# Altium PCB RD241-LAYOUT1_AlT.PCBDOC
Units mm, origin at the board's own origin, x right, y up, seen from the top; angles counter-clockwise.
Board outline 20 x 20 mm, 2 copper layers (TOP, BOTTOM), stack 0 mm thick; 24 components, 14 nets, 115 pads, 0 vias.
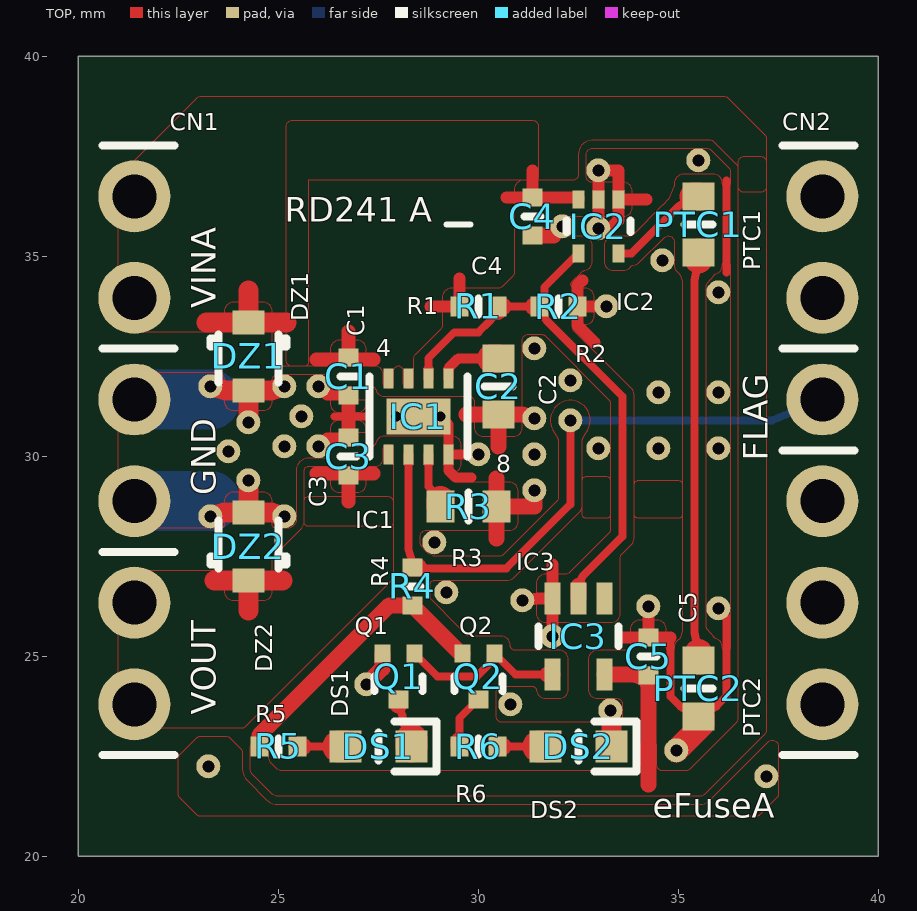
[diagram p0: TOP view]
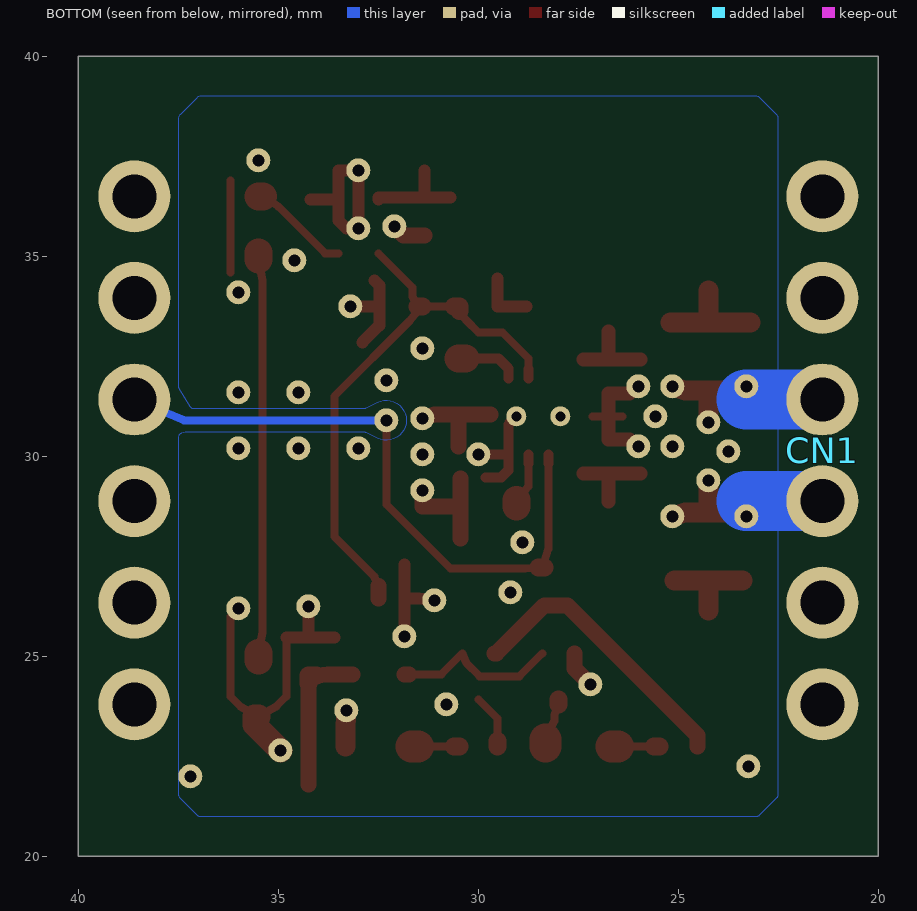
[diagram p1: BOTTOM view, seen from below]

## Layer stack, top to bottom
Top Solder: solder mask 0.0102, Solder Resist, Dk 3.5
TOP: signal copper (thickness not stored)
BOTTOM: signal copper (thickness not stored)
Bottom Solder: solder mask 0.0102, Solder Resist, Dk 3.5

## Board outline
20,20 20,40 40,40 40,20

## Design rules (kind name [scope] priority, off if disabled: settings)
AssemblyTestPointUsage [All] p0: scope1count=1 scope1_0_kind=Board scope1_0_value=Board scope2count=1 scope2_0_kind=Board scope2_0_value=Board commentlength=0
AssemblyTestpoint [All] p0: scope1count=1 scope1_0_kind=Board scope1_0_value=Board scope2count=1 scope2_0_kind=Board scope2_0_value=Board commentlength=0
Clearance [All] p0: scope1count=1 scope1_0_kind=Board scope1_0_value=Board scope2count=1 scope2_0_kind=Board scope2_0_value=Board commentlength=0 gap=0.2
Clearance [All] p1: gap=0.2 ignorepadtopadclearanceinfootprint=TRUE except(1: Arc-Hole Track-Hole SMDPad-Hole THPad-Hole Via-Hole Fill-Hole Poly-Hole Region-Hole Text-Hole)
ComponentClearance [All] p0: scope1count=1 scope1_0_kind=Board scope1_0_value=Board scope2count=1 scope2_0_kind=Board scope2_0_value=Board commentlength=0 gap=0.254 collisioncheckmode=3
DiffPairsRouting [All] p0: scope1count=1 scope1_0_kind=Board scope1_0_value=Board scope2count=1 scope2_0_kind=Board scope2_0_value=Board commentlength=0
FabricationTestPointUsage [All] p0: scope1count=1 scope1_0_kind=Board scope1_0_value=Board scope2count=1 scope2_0_kind=Board scope2_0_value=Board commentlength=0 valid=0 allowmultiple=FALSE
FabricationTestpoint [All] p0: scope1count=1 scope1_0_kind=Board scope1_0_value=Board scope2count=1 scope2_0_kind=Board scope2_0_value=Board commentlength=0 side=3 testpointundercomponent=TRUE minsize=1.016 maxsize=2.54 preferedsize=1.524 minholesize=0 maxholesize=1.016 preferedholesize=0.813 testpointgrid=0.025
FanoutControl Fanout_BGA [All] p0 off: scope1count=1 scope1_0_kind=Board scope1_0_value=Board scope2count=1 scope2_0_kind=Board scope2_0_value=Board commentlength=69 // Protel DXP Scope 1 Expression Was: IsBGA   Fanout_BGA (Default Rule)
FanoutControl Fanout_LCC [All] p0 off: scope1count=1 scope1_0_kind=Board scope1_0_value=Board scope2count=1 scope2_0_kind=Board scope2_0_value=Board commentlength=69 // Protel DXP Scope 1 Expression Was: IsLCC   Fanout_LCC (Default Rule)
FanoutControl Fanout_SOIC [All] p0 off: scope1count=1 scope1_0_kind=Board scope1_0_value=Board scope2count=1 scope2_0_kind=Board scope2_0_value=Board commentlength=71 // Protel DXP Scope 1 Expression Was: IsSOIC   Fanout_SOIC (Default Rule)
FanoutControl Fanout_Small [All] p0 off: scope1count=1 scope1_0_kind=Board scope1_0_value=Board scope2count=1 scope2_0_kind=Board scope2_0_value=Board commentlength=84 // Protel DXP Scope 1 Expression Was: (CompPinCount < 5)   Fanout_Small (Default Rule)
FanoutControl Fanout_Default [All] p0: scope1count=1 scope1_0_kind=Board scope1_0_value=Board scope2count=1 scope2_0_kind=Board scope2_0_value=Board commentlength=30 // Fanout_Default (Default Rule)
Height [All] p0: scope1count=1 scope1_0_kind=Board scope1_0_value=Board scope2count=1 scope2_0_kind=Board scope2_0_value=Board commentlength=0
HoleSize [All] p0: scope1count=1 scope1_0_kind=Board scope1_0_value=Board scope2count=1 scope2_0_kind=Board scope2_0_value=Board commentlength=0 absolutevalues=TRUE maxlimit=100 minlimit=0.001 maxpercent=80.000 minpercent=20.000
HoleSize [All] p1: absolutevalues=TRUE maxlimit=100 minlimit=0.001 maxpercent=80.000 minpercent=20.000
HoleToHoleClearance [All] p0: scope1count=1 scope1_0_kind=Board scope1_0_value=Board scope2count=1 scope2_0_kind=Board scope2_0_value=Board commentlength=0
HoleToHoleClearance [All] p1: gap=0.5 allowstackedmicrovias=FALSE
LayerPairs [All] p0: scope1count=1 scope1_0_kind=Board scope1_0_value=Board scope2count=1 scope2_0_kind=Board scope2_0_value=Board commentlength=0 enforce=TRUE
MinimumSolderMaskSliver [All] p0: scope1count=1 scope1_0_kind=Board scope1_0_value=Board scope2count=1 scope2_0_kind=Board scope2_0_value=Board commentlength=0
MinimumSolderMaskSliver [All] p1: minsoldermaskwidth=0.1
NetAntennae [All] p0: scope1count=1 scope1_0_kind=Board scope1_0_value=Board scope2count=1 scope2_0_kind=Board scope2_0_value=Board commentlength=0
NetAntennae [All] p1: netantennaetolerance=100
PasteMaskExpansion [All] p0: scope1count=1 scope1_0_kind=Board scope1_0_value=Board scope2count=1 scope2_0_kind=Board scope2_0_value=Board commentlength=0 expansion=0
PlaneClearance [All] p0: scope1count=1 scope1_0_kind=Board scope1_0_value=Board scope2count=1 scope2_0_kind=Board scope2_0_value=Board commentlength=0 clearance=0.001
PlaneClearance [All] p1: clearance=0.001
PlaneConnect [All] p0: scope1count=1 scope1_0_kind=Board scope1_0_value=Board scope2count=1 scope2_0_kind=Board scope2_0_value=Board commentlength=0 planeconnectstyle=Direct reliefexpansion=0.508 reliefentries=4 reliefconductorwidth=0.254 reliefairgap=0.254
PlaneConnect [All] p1: planeconnectstyle=Direct reliefexpansion=0.508 reliefentries=4 reliefconductorwidth=0.254 reliefairgap=0.254
PolygonConnect [All] p0: scope1count=1 scope1_0_kind=Board scope1_0_value=Board scope2count=1 scope2_0_kind=Board scope2_0_value=Board commentlength=0 connectstyle=Direct reliefconductorwidth=0.254 reliefentries=4 polygonreliefangle="90 Angle"
PolygonConnect [All] p1: connectstyle=Direct reliefconductorwidth=0.254 reliefentries=4 polygonreliefangle="90 Angle" airgapwidth=0.254
RoutingCorners [All] p0: scope1count=1 scope1_0_kind=Board scope1_0_value=Board scope2count=1 scope2_0_kind=Board scope2_0_value=Board commentlength=0 cornerstyle=45-Degree minsetback=2.54 maxsetback=2.54
RoutingLayers [All] p0: scope1count=1 scope1_0_kind=Board scope1_0_value=Board scope2count=1 scope2_0_kind=Board scope2_0_value=Board commentlength=0 top layer=Automatic bottom layer=Automatic
RoutingPriority [All] p0: scope1count=1 scope1_0_kind=Board scope1_0_value=Board scope2count=1 scope2_0_kind=Board scope2_0_value=Board commentlength=0
RoutingTopology [All] p0: scope1count=1 scope1_0_kind=Board scope1_0_value=Board scope2count=1 scope2_0_kind=Board scope2_0_value=Board commentlength=0 topology=Shortest
RoutingVias [All] p0: scope1count=1 scope1_0_kind=Board scope1_0_value=Board scope2count=1 scope2_0_kind=Board scope2_0_value=Board commentlength=0 holewidth=0.1 width=0.1 viastyle="Through Hole" minholewidth=0.001 minwidth=0.001 maxholewidth=100 maxwidth=100
RoutingVias [All] p1: holewidth=0.1 width=0.1 viastyle="Through Hole" minholewidth=0.001 minwidth=0.001 maxholewidth=100 maxwidth=100
ShortCircuit [All] p0: scope1count=1 scope1_0_kind=Board scope1_0_value=Board scope2count=1 scope2_0_kind=Board scope2_0_value=Board commentlength=0 allowed=FALSE
SilkToBoardRegionClearance [All] p0: scope1count=1 scope1_0_kind=Board scope1_0_value=Board scope2count=1 scope2_0_kind=Board scope2_0_value=Board commentlength=0
SilkToSilkClearance [All] p0: scope1count=1 scope1_0_kind=Board scope1_0_value=Board scope2count=1 scope2_0_kind=Board scope2_0_value=Board commentlength=0
SilkToSilkClearance [All] p1: silktosilkclearance=0.001
SilkToSolderMaskClearance [All] p0 off: scope1count=1 scope1_0_kind=Board scope1_0_value=Board scope2count=1 scope2_0_kind=Board scope2_0_value=Board commentlength=44 // Protel DXP Scope 1 Expression Was: IsPad
SilkToSolderMaskClearance [IsPad] p1: minsilkscreentomaskgap=0.05 clearancetoexposedcopper=TRUE
SolderMaskExpansion [All] p0: scope1count=1 scope1_0_kind=Board scope1_0_value=Board scope2count=1 scope2_0_kind=Board scope2_0_value=Board commentlength=0 expansion=0.001
SolderMaskExpansion [All] p1: expansion=0.001
UnRoutedNet [All] p0: scope1count=1 scope1_0_kind=Board scope1_0_value=Board scope2count=1 scope2_0_kind=Board scope2_0_value=Board commentlength=0
UnpouredPolygon [All] p0: scope1count=1 scope1_0_kind=Board scope1_0_value=Board scope2count=1 scope2_0_kind=Board scope2_0_value=Board commentlength=0
Width [All] p0: scope1count=1 scope1_0_kind=Board scope1_0_value=Board scope2count=1 scope2_0_kind=Board scope2_0_value=Board commentlength=0 maxlimit=1000 minlimit=2539.975 preferedwidth=0
Width [All] p1: maxlimit=1000 minlimit=2539.975 preferedwidth=0 toplayer_minwidth=0 bottomlayer_minwidth=0 minimp=50.000000 maximp=50.000000 favimp=50.000000
22 further rules are at their usual default settings.

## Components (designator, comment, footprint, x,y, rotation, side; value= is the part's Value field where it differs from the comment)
C1 "Chip1005_GS_2" Chip1005_GS_2 26.75,32 r270 top
C2 "Chip1608_GS_1" Chip1608_GS_1 30.5,31.75 r270 top
C3 "Chip1005_GS_2" Chip1005_GS_2 26.75,30 r90 top
C4 "Chip1005_GS_2" Chip1005_GS_2 31.35,36 r270 top
C5 "Chip1005_GS_2" Chip1005_GS_2 34.25,25 r90 top
CN1 "CN_I_TSW-106-07-*-S_SAMTEC" CN_I_TSW-106-07-*-S_SAMTEC 21.4,30.15 r90 bottom
DS1 "LD_S_APT1608_KB_1K-3A" LD_S_APT1608_KB_1K-3A 27.5,22.75 r180 top
DS2 "LD_S_APT1608_KB_1K-3A" LD_S_APT1608_KB_1K-3A 32.5,22.75 r180 top
DZ1 "DI_S_ESC_TS_1A-3K" DI_S_ESC_TS_1A-3K 24.25,32.5 r90 top
DZ2 "DI_S_ESC_TS_1A-3K" DI_S_ESC_TS_1A-3K 24.25,27.75 r270 top
IC1 "IC_S_SON_TCKE905NA_TS" IC_S_SON_TCKE905NA_TS 28.5,31 r180 top
IC2 "IC_S_SMD_ESV_TS" IC_S_SMD_ESV_TS 33,35.75 r180 top
IC3 "IC_S_SMD_USV_TS" IC_S_SMD_USV_TS 32.5,25.5 r180 top
PTC1 "Chip1608_GS_1" Chip1608_GS_1 35.5,35.8 r90 top
PTC2 "Chip1608_GS_1" Chip1608_GS_1 35.5,24.2 r90 top
Q1 "FET_S_VESM_TS_2G-3S-1D" FET_S_VESM_TS_2G-3S-1D 28,24.5 r180 top
Q2 "FET_S_VESM_TS_2G-3S-1D" FET_S_VESM_TS_2G-3S-1D 30,24.5 r180 top
R1 "Chip1005_GS_2" Chip1005_GS_2 30,33.75 r180 top
R2 "Chip1005_GS_2" Chip1005_GS_2 32,33.75 r180 top
R3 "Chip1608_GS_1" Chip1608_GS_1 29.75,28.75 r180 top
R4 "Chip1005_GS_2" Chip1005_GS_2 28.35,26.75 r270 top
R5 "Chip1005_GS_2" Chip1005_GS_2 25,22.75 r180 top
R6 "Chip1005_GS_2" Chip1005_GS_2 30,22.75 r180 top
? "CN_I_TSW-106-07-*-S_SAMTEC" CN_I_TSW-106-07-*-S_SAMTEC 38.6,30.15 r270 bottom

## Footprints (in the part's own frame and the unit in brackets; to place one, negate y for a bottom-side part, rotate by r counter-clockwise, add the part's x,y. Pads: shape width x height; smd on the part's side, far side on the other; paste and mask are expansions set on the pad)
Chip1005_GS_2 [mm] "KC00080BKP"
  rect 0.45x0.5 smd paste-0.6 mask+0: 1(-0.475,0) 2(0.475,0)
  silkscreen extent 0,-0.2 0,0.2
Chip1608_GS_1 [mm] "KC00080BKP"
  rect 0.7x0.8 smd paste-0.9 mask+0: 1(-0.7,0) 2(0.7,0)
  silkscreen extent 0,-0.35 0,0.35
CN_I_TSW-106-07-*-S_SAMTEC [mm] "KC00080BKP"
  round 1.8 / inner round 0 / far side round 1.8 hole 1.1 paste-1.9 mask+0: 1(6.35,0) 2(3.81,0) 3(1.27,0) 4(-1.27,0) 5(-3.81,0) 6(-6.35,0)
DI_S_ESC_TS_1A-3K [mm] "KC00080BKP"
  rect 0.6x0.8 smd paste-0.9 mask+0: 1(-0.85,0) 3(0.85,0)
  silkscreen extent -0.65,-0.95 0.55,0.95
FET_S_VESM_TS_2G-3S-1D [mm] "KC00080BKP"
  rect 0.5x0.45 smd paste-0.6 mask+0: 1(0,0.575)
  rect 0.4x0.45 smd paste-0.55 mask+0: 2(-0.4,-0.575) 3(0.4,-0.575)
  silkscreen extent -0.6,0 0.6,0.37
IC_S_SMD_ESV_TS [mm] "KC00080BKP"
  rect 0.3x0.45 smd paste-0.55 mask+0: 1(-0.5,-0.675) 2(0,-0.675) 3(0.5,-0.675) 4(0.5,0.675) 5(-0.5,0.675)
  silkscreen extent -0.8,-0.14 0.8,0.14
IC_S_SMD_USV_TS [mm] "KC00080BKP"
  rect 0.4x0.8 smd paste-0.9 mask+0: 1(-0.65,-0.95) 2(0,-0.95) 3(0.65,-0.95) 4(0.65,0.95) 5(-0.65,0.95)
  silkscreen extent -1,-0.24 1,0.24
IC_S_SON_TCKE905NA_TS [mm] "KC00080BKP"
  rect 0.25x0.5 smd paste-0.6 mask+0: 1(-0.75,-0.95) 2(-0.25,-0.95) 3(0.25,-0.95) 4(0.75,-0.95) 5(0.75,0.95) 6(0.25,0.95) 7(-0.25,0.95) 8(-0.75,0.95)
  rect 1.6x0.9 smd paste-1.7 mask+0: 9(0,0)
  silkscreen extent -1.23,-1 1.22,1
LD_S_APT1608_KB_1K-3A [mm] "KC00080BKP"
  rect 0.8x0.8 smd paste-0.9 mask+0: 1(-0.825,0) 3(0.825,0)
  silkscreen extent 0,-0.35 0,0.35

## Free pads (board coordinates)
  round 0.6 / inner round 0 / far side round 0.6 hole 0.3 paste-0.6 mask+0: ""(23.25,22.25) ""(23.3,28.5) ""(23.3,31.75) ""(23.75,30.125) ""(24.25,29.4) ""(24.25,30.85) ""(25.15,28.5) ""(25.15,30.25) ""(25.15,31.75) ""(25.575,31) ""(26,30.25) ""(26,31.75) ""(27.2,24.3) ""(28.9,27.85) ""(29.2,26.6) ""(30,30.05) ""(30.8,23.8) ""(31.1,26.4) ""(31.4,29.15) ""(31.4,30.05) ""(31.4,30.95) ""(31.4,32.7) ""(31.85,25.5) ""(32.1,35.75) ""(32.3,30.9) ""(32.3,31.9) ""(33,30.2) ""(33,35.7) ""(33,37.15) ""(33.2,33.75) ""(33.3,23.65) ""(34.25,26.25) ""(34.5,30.2) ""(34.5,31.6) ""(34.6,34.9) ""(34.95,22.65) ""(35.5,37.4) ""(36,26.2) ""(36,30.2) ""(36,31.6) ""(36,34.1) ""(37.2,22)
  round 0.5 / inner round 0 / far side round 0.5 hole 0.25 paste-0.5 mask+0: ""(27.95,31) ""(29.05,31)

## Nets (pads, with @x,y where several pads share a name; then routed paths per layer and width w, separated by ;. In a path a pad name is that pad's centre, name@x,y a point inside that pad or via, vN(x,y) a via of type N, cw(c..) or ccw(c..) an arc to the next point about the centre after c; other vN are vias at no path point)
FLAG_A: ?.4 IC1.6 pad.@32.3,30.9 R4.1 | length 15.8
  TOP w0.2: IC1.6@28.25,29.819 28.25,27.689 R4.1@28.35,27.367 ; R4.1@28.492,27.225 28.828,27.2 30.7,27.2 32.3,28.8 pad.@32.3,30.9
  TOP w0.25: IC1.6@28.25,29.819 IC1.6
  TOP w0.45: R4.1 R4.1@28.492,27.225
  BOTTOM w0.2: pad.@32.3,30.9 37.354,30.9 ?.4
GND_A: C1.2 C2.2 C3.2 C4.2 C5.2 CN1.3 CN1.4 DS2.1 DZ1.1 DZ2.1 IC1.8 IC1.9 IC2.1 IC2.2 IC3.3 pad.@23.3,28.5 pad.@23.3,31.75 pad.@23.25,22.25 pad.@23.75,30.125 pad.@24.25,29.4 pad.@24.25,30.85 pad.@25.15,28.5 pad.@25.15,30.25 pad.@25.15,31.75 pad.@25.575,31 pad.@26,30.25 pad.@26,31.75 pad.@27.2,24.3 pad.@27.95,31 pad.@28.9,27.85 pad.@29.2,26.6 pad.@29.05,31 pad.@30,30.05 pad.@30.8,23.8 pad.@31.1,26.4 pad.@31.4,29.15 pad.@31.4,30.05 pad.@31.4,30.95 pad.@31.4,32.7 pad.@31.85,25.5 pad.@32.1,35.75 pad.@32.3,31.9 pad.@33,30.2 pad.@33,35.7 pad.@33,37.15 pad.@33.2,33.75 pad.@33.3,23.65 pad.@34.5,30.2 pad.@34.5,31.6 pad.@34.6,34.9 pad.@34.25,26.25 pad.@34.95,22.65 pad.@35.5,37.4 pad.@36,26.2 pad.@36,30.2 pad.@36,31.6 pad.@36,34.1 pad.@37.2,22 PTC2.1 Q1.3 R2.1 R3.1 | length 43.2
  TOP w0.2: 26.4,31 26.75,31 27.15,31 ; 34.8,25.475 34.8,24 35.05,23.75 PTC2.1 35.95,23.75 36.2,24 pad.@36.2,26 ; 36.2,34.6 36.2,36.9
  TOP w0.25: pad.@29.05,31 29.25,30.8 IC1.8 ; 29.825,29.475 29.425,29.475 29.25,29.65 IC1.8 ; pad.@30,30.05 IC1.8
  TOP w0.3: pad.@31.1,26.4 31.487,26.45 IC3.3 ; pad.@31.85,25.5 IC3.3 ; 31.85,27.3 IC3.3 ; 32.6,34.4 32.475,34.275 R2.1 ; 32.9,32.85 32.475,33.275 R2.1 ; pad.@33.2,33.75 R2.1 ; 33.6,25.475 C5.2 ; 34.2,36.425 IC2.1 ; pad.@34.25,26.25 C5.2 ; 34.8,25.475 C5.2 ; IC2.1 33.5,35.9 33.3,35.7 33,35.7 IC2.2 33,37.15 33.5,37.15 IC2.1
  TOP w0.35: pad.@26.225,30.425 26.75,30.425 C3.2 26.75,31 C1.2 26.75,31.575 pad.@26.225,31.575
  TOP w0.4: pad.@27.2,24.3 27.6,24.7 Q1.3 ; 29.7,31.05 C2.2 ; 30.45,27.95 R3.1 ; 30.45,29.45 R3.1 ; 30.5,30.25 C2.2 ; C4.2 31.875,35.525 pad.@32.1,35.75 ; pad.@31.4,29.15 31.4,28.75 R3.1 ; pad.@31.4,30.95 31.086,31.05 C2.2
  TOP w0.5: pad.@23.3,28.5 23.677,28.6 DZ2.1 ; pad.@23.3,31.75 23.677,31.65 DZ1.1 ; pad.@24.25,29.4 DZ2.1 ; pad.@24.25,30.85 DZ1.1 ; pad.@25.15,28.5 24.836,28.6 DZ2.1 ; pad.@25.15,31.75 24.836,31.65 DZ1.1 ; pad.@33.3,23.65 33.325,23.261 DS2.1
  TOP w0.6: pad.@34.95,22.65 35.6,23.3 35.6,23.5 PTC2.1
  BOTTOM w1.5: CN1.4 23.3,28.88 ; CN1.3 23.3,31.42
N439568: IC1.2 IC2.4 IC3.2 R1.1 R2.2 | length 14.1
  TOP w0.2: IC1.2@28.75,32.181 28.75,32.45 29.4,33.1 30,33.1 30.297,33.397 R1.1@30.475,33.629 ; R1.1@30.604,33.75 R2.2@31.396,33.75 ; R2.2@31.525,33.621 31.707,33.393 33.6,31.5 33.6,27.992 32.6,26.992 IC3.2@32.5,26.752 ; R2.2 31.65,34.014 31.65,34.225 IC2.4
  TOP w0.25: IC1.2 IC1.2@28.75,32.181
  TOP w0.4: IC3.2 IC3.2@32.5,26.752
  TOP w0.45: R1.1@30.475,33.629 R1.1 R1.1@30.604,33.75 ; R2.2@31.396,33.75 R2.2
N439874: C2.1 IC1.1 | length 1.6
  TOP w0.25: IC1.1 29.25,32.2 29.5,32.45 C2.1@30.323,32.45
  TOP w0.7: C2.1@30.323,32.45 C2.1
N440585: IC2.5 PTC1.2 | length 2.6
  TOP w0.2: IC2.5 33.828,35.075 35.003,36.25 PTC1.2@35.383,36.5
  TOP w0.7: PTC1.2@35.383,36.5 PTC1.2
N440589: PTC1.1 PTC2.2 | length 10.2
  TOP w0.2: PTC2.2@35.5,25.083 35.4,25.599 35.4,34.401 PTC1.1@35.5,34.917
  TOP w0.7: PTC2.2 PTC2.2@35.5,25.083 ; PTC1.1@35.5,34.917 PTC1.1
N441229: IC3.4 Q1.2 Q2.2 | length 4.2
  TOP w0.2: Q1.2 28.975,24.5 29.965,24.5 30.3,24.835 Q2.2 30.925,24.55 IC3.4@31.727,24.55
  TOP w0.4: IC3.4@31.727,24.55 IC3.4
N442165: Q2.1 R6.2 | length 1.4
  TOP w0.2: R6.2@29.525,22.879 29.525,23.45 Q2.1
  TOP w0.45: R6.2 R6.2@29.525,22.879
N444370: IC1.7 R3.2 | length 1.4
  TOP w0.2: IC1.7@28.75,29.819 28.75,29.25 R3.2@29.05,28.908
  TOP w0.25: IC1.7@28.75,29.819 IC1.7
  TOP w0.7: R3.2 R3.2@29.05,28.908
N450467: DS1.3 R5.1 | length 1.2
  TOP w0.2: R5.1@25.604,22.75 DS1.3@26.506,22.75
  TOP w0.45: R5.1 R5.1@25.604,22.75
  TOP w0.8: DS1.3@26.506,22.75 DS1.3
N450546: DS1.1 Q1.1 | length 1.2
  TOP w0.2: Q1.1@28,23.796 28.1,23.521 28.1,23.388 DS1.1@28.325,22.919
  TOP w0.45: Q1.1@28,23.796 Q1.1
  TOP w0.8: DS1.1 DS1.1@28.325,22.919
N475569: DS2.3 R6.1 | length 1.2
  TOP w0.2: R6.1@30.604,22.75 DS2.3@31.506,22.75
  TOP w0.45: R6.1 R6.1@30.604,22.75
  TOP w0.8: DS2.3@31.506,22.75 DS2.3
VINA_A: C1.1 C4.1 C5.1 CN1.1 CN1.2 DZ1.3 IC1.3 IC1.4 IC2.3 IC3.5 Q2.3 R1.2 R4.2 R5.2 | length 19.9
  TOP w0.3: 28.8,33.75 R1.2 29.525,34.45 ; 30.7,36.475 C4.1 ; 31.35,37.15 C4.1 ; IC2.3 32.5,36.475 C4.1
  TOP w0.35: 25.95,32.425 C1.1@26.75,32.425 ; 26.75,33.125 C1.1 C1.1@26.75,32.425 ; 27.375,32.425 C1.1@26.75,32.425
  TOP w0.4: R5.2 24.525,23.025 27.775,26.275 R4.2 29.55,25.075 Q2.3 ; IC3.5 33.753,24.55 C5.1@34.044,24.525 ; 34.25,21.8 C5.1@34.25,24.319
  TOP w0.45: C5.1@34.044,24.525 C5.1 C5.1@34.25,24.319
  TOP w0.5: 23.2,33.35 DZ1.3 ; 24.25,34.15 DZ1.3 ; 25.2,33.35 DZ1.3
VOUT_A: C3.1 CN1.5 CN1.6 DZ2.3 IC1.5 | length 4.6
  TOP w0.35: 25.95,29.575 C3.1@26.75,29.575 ; 26.75,28.875 C3.1 C3.1@26.75,29.575 ; 27.375,29.575 C3.1@26.75,29.575
  TOP w0.5: 23.4,26.9 DZ2.3 ; 24.25,26.15 DZ2.3 ; 25.1,26.9 DZ2.3
pads on no net: ?.1 ?.2 ?.3 ?.5 ?.6 IC3.1

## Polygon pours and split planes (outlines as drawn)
GND_A on TOP "TOP1" (solid, pour order 3): 23.041,21 cw(c23.041,21.1) 22.971,21.029 22.529,21.471 cw(c22.6,21.541) 22.5,21.541 22.5,22.459 cw(c22.6,22.459) 22.529,22.529 22.971,22.971 cw(c23.041,22.9) 23.041,23 23.688,23 cw(c23.688,22.85) 23.794,22.956 24.056,22.694 cw(c23.95,22.588) 24.1,22.588 24.1,22.183 ccw(c24.5,22.183) 24.217,21.9 24.7,21.417 ccw(c24.983,21.7) 24.983,21.3 35.5,21.3 cw(c35.505,21.2) 35.505,21.3 35.538,21.3 ccw(c35.538,21.65) 35.786,21.403 37.244,22.861 cw(c37.35,22.755) 37.5,22.755 37.5,21.541 cw(c37.4,21.541) 37.471,21.471 37.029,21.029 cw(c36.959,21.1) 36.959,21
VINA_A on TOP "TOP2" (solid, pour order 4): 24.983,21.5 cw(c24.983,21.7) 24.841,21.559 24.359,22.041 cw(c24.5,22.183) 24.3,22.183 24.3,22.7 cw(c24.5,22.7) 24.5,22.9 24.55,22.9 cw(c24.55,22.7) 24.75,22.7 24.75,22.483 ccw(c24.95,22.483) 24.809,22.341 24.941,22.209 ccw(c25.083,22.35) 25.083,22.15 33.9,22.15 ccw(c33.9,22.3) 34.05,22.3 34.05,22.75 cw(c34.2,22.75) 34.2,22.9 34.3,22.9 cw(c34.3,22.75) 34.45,22.75 34.45,22.3 ccw(c34.6,22.3) 34.6,22.15 35.188,22.15 ccw(c35.188,22.3) 35.294,22.194 36.456,23.356 ccw(c36.35,23.462) 36.5,23.462 36.5,23.94 36.5,23.942 36.5,23.95 36.5,26 36.5,26.006 36.5,26.008 36.5,26.8 36.5,37.35 cw(c36.65,37.35) 36.65,37.5 37.05,37.5 cw(c37.05,37.35) 37.2,37.35 37.2,23.162 cw(c37.05,23.162) 37.156,23.056 35.644,21.544 cw(c35.538,21.65) 35.538,21.5
VOUT_A on TOP "TOP3" (solid, pour order 5): 21.2,23.2 cw(c21.2,23.4) 21,23.4 21,26.95 cw(c21.2,26.95) 21.2,27.15 23.45,27.15 cw(c23.45,26.95) 23.65,26.95 23.65,26.625 ccw(c23.875,26.625) 23.875,26.4 24.625,26.4 ccw(c24.625,26.625) 24.85,26.625 24.85,27.405 cw(c25,27.405) 24.894,27.511 25.548,28.165 ccw(c25.3,28.412) 25.65,28.412 25.65,28.9 cw(c25.75,28.9) 25.75,29 27.725,29 cw(c27.725,28.85) 27.875,28.85 27.875,27.003 cw(c27.725,27.003) 27.831,26.897 24.178,23.244 cw(c24.072,23.35) 24.072,23.2 21.2,23.2
GND_A on TOP "TOP4" (solid, pour order 6): 30.6,23.35 cw(c30.6,23.5) 30.45,23.5 30.45,24.1 cw(c30.6,24.1) 30.6,24.25 31.351,24.25 cw(c31.351,24.15) 31.451,24.158 31.451,24.157 ccw(c31.675,24.175) 31.675,23.95 32.025,23.95 ccw(c32.025,24.175) 32.25,24.175 32.25,24.925 ccw(c32.025,24.925) 32.025,25.15 30.925,25.15 cw(c30.925,25.275) 30.8,25.275 ccw(c30.575,25.275) 30.575,25.5 29.803,25.5 cw(c29.803,25.65) 29.697,25.544 29.158,26.082 29.157,26.083 28.844,26.397 cw(c28.95,26.503) 28.8,26.503 28.8,26.8 cw(c28.9,26.8) 28.9,26.9 30.7,26.9 ccw(c30.7,27.2) 30.912,26.988 32.512,28.588 ccw(c32.3,28.8) 32.6,28.8 32.6,29.4 cw(c32.7,29.4) 32.7,29.5 33.2,29.5 cw(c33.2,29.4) 33.3,29.4 33.3,28.158 cw(c33.2,28.158) 33.271,28.087 32.389,27.206 32.389,27.205 32.271,27.088 cw(c32.2,27.159) 32.258,27.078 cw(c32.171,27.2) 32.171,27.05 31.675,27.05 ccw(c31.675,26.825) 31.45,26.825 31.45,26.075 ccw(c31.675,26.075) 31.675,25.85 33.325,25.85 ccw(c33.325,26.075) 33.55,26.075 33.55,27.456 cw(c33.7,27.456) 33.594,27.562 33.595,27.563 33.811,27.779 33.812,27.78 33.813,27.781 ccw(c33.6,27.992) 33.9,27.992 33.9,29.3 cw(c34,29.3) 34,29.4 35,29.4 cw(c35,29.3) 35.1,29.3 35.1,25.66 cw(c35,25.66) 35.095,25.63 35.044,25.468 cw(c34.949,25.498) 35.02,25.428 cw(c34.949,25.498) 35.003,25.414 ccw(c35.125,25.225) 34.9,25.23 cw(c34.8,25.232) 34.7,25.232 34.7,25.675 ccw(c34.475,25.675) 34.475,25.9 34.025,25.9 ccw(c34.025,25.675) 33.8,25.675 33.8,25.3 cw(c33.65,25.3) 33.65,25.15 32.975,25.15 ccw(c32.975,24.925) 32.75,24.925 32.75,24.175 ccw(c32.975,24.175) 32.975,23.95 33.45,23.95 cw(c33.45,23.8) 33.6,23.8 33.6,23.5 cw(c33.45,23.5) 33.45,23.35
GND_A on TOP "TOP5" (solid, pour order 7): 36.1,25.229 ccw(c35.875,25.225) 35.94,25.44 cw(c35.969,25.536) 35.892,25.473 35.723,25.679 cw(c35.8,25.742) 35.7,25.742 35.7,34.258 cw(c35.8,34.258) 35.723,34.321 35.892,34.527 cw(c35.969,34.464) 35.94,34.56 ccw(c35.875,34.775) 36.1,34.772 cw(c36.2,34.771) 36.3,34.771 36.3,26.8 36.3,26.008 36.3,26.002 36.3,26 36.3,25.23 cw(c36.2,25.23) 36.1,25.229
GND_A on TOP "TOP6" (solid, pour order 8): 28.921,27.5 cw(c28.921,27.6) 28.877,27.51 28.758,27.568 cw(c28.802,27.658) 28.732,27.586 ccw(c28.575,27.425) 28.707,27.607 28.706,27.608 cw(c28.764,27.689) 28.685,27.629 28.684,27.63 28.683,27.631 28.68,27.634 28.572,27.768 cw(c28.65,27.831) 28.55,27.831 28.55,28 cw(c28.7,28) 28.7,28.15 30.775,28.15 ccw(c30.775,28.375) 31,28.375 31,29.125 ccw(c30.775,29.125) 30.775,29.35 29.45,29.35 cw(c29.45,29.45) 29.379,29.379 29.326,29.433 cw(c29.396,29.503) 29.383,29.602 ccw(c29.35,29.825) 29.575,29.825 29.575,30.275 ccw(c29.35,30.275) 29.35,30.5 27.65,30.5 ccw(c27.65,30.275) 27.431,30.327 cw(c27.334,30.35) 27.429,30.318 cw(c27.334,30.35) 27.334,30.25 26.85,30.25 cw(c26.85,30.35) 26.75,30.35 26.75,30.5 cw(c26.85,30.5) 26.85,30.6 27.2,30.6 27.2,30.675 ccw(c26.975,30.675) 26.979,30.9 cw(c26.98,31) 26.979,31.1 ccw(c26.975,31.325) 27.2,31.325 27.2,31.4 26.85,31.4 cw(c26.85,31.5) 26.75,31.5 26.75,31.65 cw(c26.85,31.65) 26.85,31.75 27.334,31.75 cw(c27.334,31.65) 27.429,31.682 cw(c27.334,31.65) 27.431,31.672 ccw(c27.65,31.725) 27.65,31.5 29.75,31.5 cw(c29.75,31.35) 29.9,31.35 29.9,30.725 ccw(c30.125,30.725) 30.125,30.5 30.875,30.5 ccw(c30.875,30.725) 31.1,30.725 31.1,32.9 cw(c31.25,32.9) 31.25,33.05 31.584,33.05 cw(c31.584,32.95) 31.655,33.021 33.271,31.405 cw(c33.2,31.334) 33.3,31.334 33.3,28.55 cw(c33.2,28.55) 33.2,28.45 32.7,28.45 cw(c32.7,28.55) 32.6,28.55 32.6,30.4 cw(c32.7,30.4) 32.611,30.444 cw(c32.7,30.4) 32.614,30.451 32.729,30.644 32.73,30.644 32.731,30.646 ccw(c32.3,30.9) 31.869,30.646 31.87,30.644 31.871,30.644 31.986,30.451 cw(c31.9,30.4) 32,30.4 32,29.653 32,29.652 32,29.65 32,28.966 cw(c31.9,28.966) 31.971,28.895 30.605,27.529 cw(c30.534,27.6) 30.534,27.5
GND_A on TOP "TOP7" (solid, pour order 9): 21.2,28.2 cw(c21.2,28.4) 21,28.4 21,31.9 cw(c21.2,31.9) 21.2,32.1 23.45,32.1 cw(c23.45,31.9) 23.65,31.9 23.65,31.375 ccw(c23.875,31.375) 23.875,31.15 24.625,31.15 ccw(c24.625,31.375) 24.85,31.375 24.85,31.9 cw(c25,31.9) 25,32.05 26.15,32.05 cw(c26.15,31.9) 26.3,31.9 26.3,31.325 ccw(c26.525,31.325) 26.521,31.1 cw(c26.52,31) 26.521,30.9 ccw(c26.525,30.675) 26.3,30.675 26.3,30.1 cw(c26.15,30.1) 26.15,29.95 25.75,29.95 ccw(c25.75,29.65) 25.45,29.65 25.45,28.412 cw(c25.3,28.412) 25.449,28.391 25.448,28.39 cw(c25.3,28.412) 25.406,28.306 25.344,28.244 cw(c25.238,28.35) 25.238,28.2 24.949,28.2 cw(c24.949,28.3) 24.917,28.205 cw(c24.949,28.3) 24.849,28.3 cw(c24.949,28.3) 24.849,28.308 ccw(c24.625,28.325) 24.85,28.325 24.85,28.875 ccw(c24.625,28.875) 24.625,29.1 23.875,29.1 ccw(c23.875,28.875) 23.65,28.875 23.65,28.325 ccw(c23.875,28.325) 23.651,28.308 cw(c23.551,28.3) 23.651,28.3 cw(c23.551,28.3) 23.551,28.2
VOUT_A on TOP "TOP8" (solid, pour order 10): 25.746,28.25 cw(c25.746,28.35) 25.647,28.364 ccw(c25.3,28.412) 25.65,28.412 25.65,29.65 cw(c25.75,29.65) 25.75,29.75 26.2,29.75 cw(c26.2,29.65) 26.3,29.65 26.3,29.325 ccw(c26.525,29.325) 26.525,29.1 26.975,29.1 ccw(c26.975,29.325) 27.2,29.325 27.2,29.65 cw(c27.3,29.65) 27.3,29.75 27.425,29.75 ccw(c27.425,29.95) 27.625,29.95 27.625,30.175 cw(c27.75,30.175) 27.875,30.175 27.875,28.35 cw(c27.775,28.35) 27.775,28.25
GND_A on TOP "TOP9" (solid, pour order 11): 34,28.45 cw(c34,28.55) 33.9,28.55 33.9,31.5 ccw(c33.6,31.5) 33.812,31.712 32.395,33.129 cw(c32.466,33.2) 32.466,33.3 32.675,33.3 ccw(c32.675,33.525) 32.9,33.525 32.9,33.975 ccw(c32.675,33.975) 32.675,34.2 32.416,34.2 cw(c32.416,34.3) 32.345,34.371 32.569,34.594 cw(c32.639,34.524) 32.574,34.599 32.609,34.629 cw(c32.674,34.554) 32.659,34.653 ccw(c32.625,34.875) 32.85,34.875 32.85,35.275 ccw(c32.625,35.275) 32.625,35.5 32.05,35.5 cw(c32.05,35.65) 31.9,35.65 31.9,35.85 cw(c32.05,35.85) 32.05,36 33.625,36 ccw(c33.625,36.225) 33.85,36.225 33.85,36.625 ccw(c33.625,36.625) 33.625,36.85 32.85,36.85 cw(c32.85,37) 32.7,37 32.7,37.55 cw(c32.85,37.55) 32.846,37.7 32.849,37.7 35.491,37.7 35.495,37.7 35.497,37.7 35.498,37.7 35.502,37.7 35.503,37.7 35.504,37.7 35.509,37.7 35.726,37.7 cw(c35.726,37.6) 35.796,37.671 36.271,37.196 cw(c36.2,37.126) 36.3,37.126 36.3,36.833 cw(c36.2,36.833) 36.1,36.83 ccw(c35.875,36.825) 35.875,37.05 35.125,37.05 ccw(c35.125,36.825) 34.9,36.825 34.9,36.787 cw(c34.8,36.787) 34.89,36.743 34.888,36.74 34.888,36.739 34.879,36.72 34.879,36.719 34.878,36.717 34.877,36.716 34.758,36.44 cw(c34.666,36.479) 34.737,36.408 34.617,36.288 cw(c34.546,36.358) 34.6,36.274 33.87,35.544 cw(c33.764,35.65) 33.764,35.5 33.375,35.5 ccw(c33.375,35.275) 33.15,35.275 33.15,34.875 ccw(c33.375,34.875) 33.37,34.65 33.375,34.65 33.625,34.65 ccw(c33.625,34.875) 33.804,34.739 cw(c33.884,34.679) 33.814,34.75 cw(c33.884,34.679) 33.87,34.778 ccw(c33.828,35.075) 34.04,34.863 34.644,35.466 cw(c34.75,35.36) 34.9,35.36 34.9,34.775 ccw(c35.125,34.775) 35.003,34.586 cw(c34.949,34.502) 35.044,34.532 35.095,34.371 35.095,34.37 cw(c35,34.34) 35.1,34.34 35.1,28.55 cw(c35,28.55) 35,28.45
VINA_A on TOP "TOP10" (solid, pour order 12): 27.625,32.05 ccw(c27.425,32.05) 27.425,32.25 27.3,32.25 cw(c27.3,32.35) 27.2,32.35 27.2,32.675 ccw(c26.975,32.675) 26.975,32.9 26.525,32.9 ccw(c26.525,32.675) 26.3,32.675 26.3,32.35 cw(c26.2,32.35) 26.2,32.25 25.35,32.25 cw(c25.35,32.4) 25.2,32.4 25.2,38.25 cw(c25.35,38.25) 25.35,38.4 31.35,38.4 cw(c31.35,38.25) 31.5,38.25 31.5,37 cw(c31.4,37) 31.4,36.9 31.125,36.9 ccw(c31.125,36.675) 30.9,36.675 30.9,34.612 cw(c30.75,34.612) 30.856,34.506 30.594,34.244 cw(c30.488,34.35) 30.488,34.2 29.325,34.2 ccw(c29.325,33.975) 29.1,33.975 29.1,33.525 ccw(c29.325,33.525) 29.102,33.492 cw(c29.004,33.477) 29.1,33.45 29.1,33.287 cw(c28.95,33.287) 29.056,33.181 28.419,32.544 ccw(c28.525,32.438) 28.375,32.438 28.375,31.825 cw(c28.25,31.825) 28.125,31.825 28.125,32.125 ccw(c28,32.125) 27.875,32.125 27.875,31.825 cw(c27.75,31.825) 27.625,31.825
VINA_A on TOP "TOP11" (solid, pour order 13): 25,32.25 cw(c25,32.4) 24.85,32.4 24.85,33.625 ccw(c24.625,33.625) 24.625,33.85 23.875,33.85 ccw(c23.875,33.625) 23.65,33.625 23.65,33.2 cw(c23.55,33.2) 23.55,33.1 21.383,33.1 cw(c21.383,33.3) 21.241,33.159 21.059,33.341 cw(c21.2,33.483) 21,33.483 21,36.938 cw(c21.15,36.938) 21.044,37.044 22.956,38.956 cw(c23.062,38.85) 23.062,39 36.138,39 cw(c36.138,38.85) 36.244,38.956 37.156,38.044 cw(c37.05,37.938) 37.2,37.938 37.2,36.75 cw(c37.05,36.75) 37.05,36.6 36.65,36.6 cw(c36.65,36.75) 36.5,36.75 36.5,37.188 ccw(c36.35,37.188) 36.456,37.294 35.894,37.856 ccw(c35.788,37.75) 35.788,37.9 35.728,37.9 35.726,37.9 35.509,37.9 35.507,37.9 35.506,37.9 35.505,37.9 35.504,37.9 35.503,37.9 35.497,37.9 35.496,37.9 35.495,37.9 35.494,37.9 35.493,37.9 35.491,37.9 32.849,37.9 32.841,37.9 ccw(c32.85,37.55) 32.5,37.55 32.5,37.05 cw(c32.35,37.05) 32.35,36.9 25.75,36.9 25.75,32.35 cw(c25.65,32.35) 25.65,32.25 25.207,32.25 25.206,32.25 25.194,32.25 25.193,32.25
GND_A on BOTTOM "BOTTOM12" (solid, pour order 2): 23.041,21 cw(c23.041,21.1) 22.971,21.029 22.529,21.471 cw(c22.6,21.541) 22.5,21.541 22.5,38.438 cw(c22.65,38.438) 22.544,38.544 22.956,38.956 cw(c23.062,38.85) 23.062,39 36.938,39 cw(c36.938,38.85) 37.044,38.956 37.456,38.544 cw(c37.35,38.438) 37.5,38.438 37.5,31.753 cw(c37.4,31.753) 37.486,31.701 37.214,31.249 cw(c37.128,31.3) 37.128,31.2 32.844,31.2 cw(c32.844,31.3) 32.799,31.21 32.524,31.347 ccw(c32.3,30.9) 32.524,30.453 32.799,30.59 cw(c32.844,30.5) 32.844,30.6 37.306,30.6 cw(c37.306,30.5) 37.33,30.597 37.424,30.574 cw(c37.4,30.477) 37.5,30.477 37.5,21.541 cw(c37.4,21.541) 37.471,21.471 37.029,21.029 cw(c36.959,21.1) 36.959,21
no net on Top Overlay "TOPOVERLAY13" (solid, pour order 0): 22,38.4 20.8,38.4 21.4,39.5

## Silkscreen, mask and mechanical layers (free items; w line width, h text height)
Top Overlay:
  lines w0.15: 29.2,35.8 29.8,35.8
  lines w0.2: 20.6,22.53 22.4,22.53 ; 20.6,27.61 22.4,27.61 ; 20.6,32.69 22.4,32.69 ; 20.6,37.77 22.4,37.77 ; 27.9,22.125 28.95,22.125 28.95,23.375 27.9,23.375 ; 32.9,22.125 33.95,22.125 33.95,23.375 32.9,23.375 ; 37.6,22.53 39.4,22.53 ; 37.6,30.15 39.4,30.15 ; 37.6,32.69 39.4,32.69 ; 37.6,37.77 39.4,37.77
  text "RD241 A" at 25.155,35.87 h0.61
  text "VINA" at 23.44,33.7 h0.61 r90
  text "FLAG" at 37.24,29.89 h0.61 r90
  text "GND" at 23.44,29.025 h0.61 r90
  text "VOUT" at 23.44,23.54 h0.61 r90
  text "eFuseA" at 34.36,20.97 h0.61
